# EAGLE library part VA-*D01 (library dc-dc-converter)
DC DC Converter Dual Separate Output, 1 Watt Motien Technology Co.,Ltd. Source: VA-D01.pdf
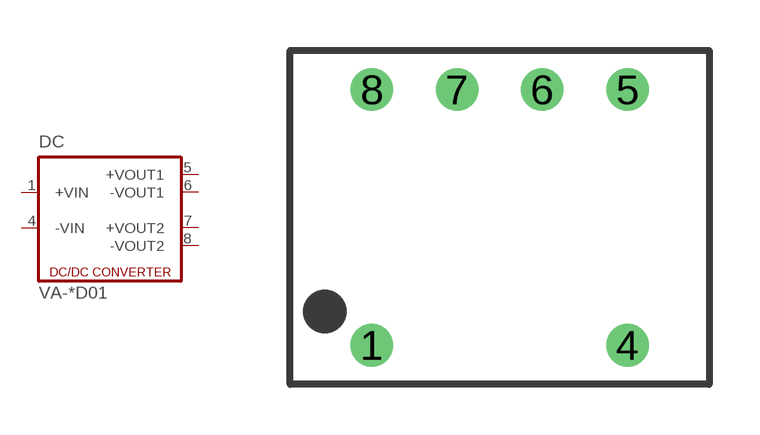
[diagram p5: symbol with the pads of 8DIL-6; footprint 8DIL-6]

Designator prefix DC

## VA-0505D01 (OC_FARNELL: unknown; OC_NEWARK: unknown), VA-0509D01 (OC_FARNELL: unknown; OC_NEWARK: unknown), VA-0512D01 (OC_FARNELL: unknown; OC_NEWARK: unknown), VA-0515D01 (OC_FARNELL: unknown; OC_NEWARK: unknown), VA-0524D01 (OC_FARNELL: unknown; OC_NEWARK: unknown), VA-1205D01 (OC_FARNELL: unknown; OC_NEWARK: unknown), VA-1209D01 (OC_FARNELL: unknown; OC_NEWARK: unknown), VA-1212D01 (OC_FARNELL: unknown; OC_NEWARK: unknown), VA-1215D01 (OC_FARNELL: unknown; OC_NEWARK: unknown), VA-1224D01 (OC_FARNELL: unknown; OC_NEWARK: unknown), VA-2405D01 (OC_FARNELL: unknown; OC_NEWARK: unknown), VA-2409D01 (OC_FARNELL: unknown; OC_NEWARK: unknown), VA-2412D01 (OC_FARNELL: unknown; OC_NEWARK: unknown), VA-2415D01 (OC_FARNELL: unknown; OC_NEWARK: unknown), VA-2424D01 (OC_FARNELL: unknown; OC_NEWARK: unknown)  [8DIL-6]
1  +VIN  pas
4  -VIN  pas
5  +VOUT1  pas
6  -VOUT1  pas
7  +VOUT2  pas
8  -VOUT2  pas

## Footprint 8DIL-6 (pad centres in mm)
8 DIL Package 6 Pads Motien Technology Co.,Ltd. Source: VA-D01.pdf
drill 0.7 pad 1.27 round: 1 -3.81,-3.81; 4 3.81,-3.81; 5 3.81,3.81; 6 1.27,3.81; 7 -1.27,3.81; 8 -3.81,3.81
